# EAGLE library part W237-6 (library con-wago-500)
WAGO SCREW CLAMP
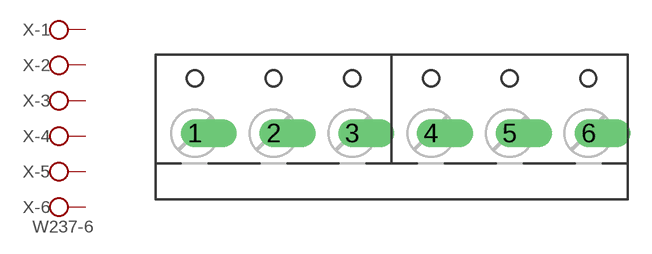
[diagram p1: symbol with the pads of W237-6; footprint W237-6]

Designator prefix X; gates -1=KL -2=KL -3=KL -4=KL -5=KL -6=KL+V

## W237-6  [W237-6]
1  -1:KL  pas
2  -2:KL  pas
3  -3:KL  pas
4  -4:KL  pas
5  -5:KL  pas
6  -6:KL  pas

## Footprint W237-6 (pad centres in mm)
WAGO SCREW CLAMP
drill 1.194 offset: 1 -12.5,-1.27; 2 -7.5,-1.27; 3 -2.5,-1.27; 4 2.5,-1.27; 5 7.5,-1.27; 6 12.5,-1.27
